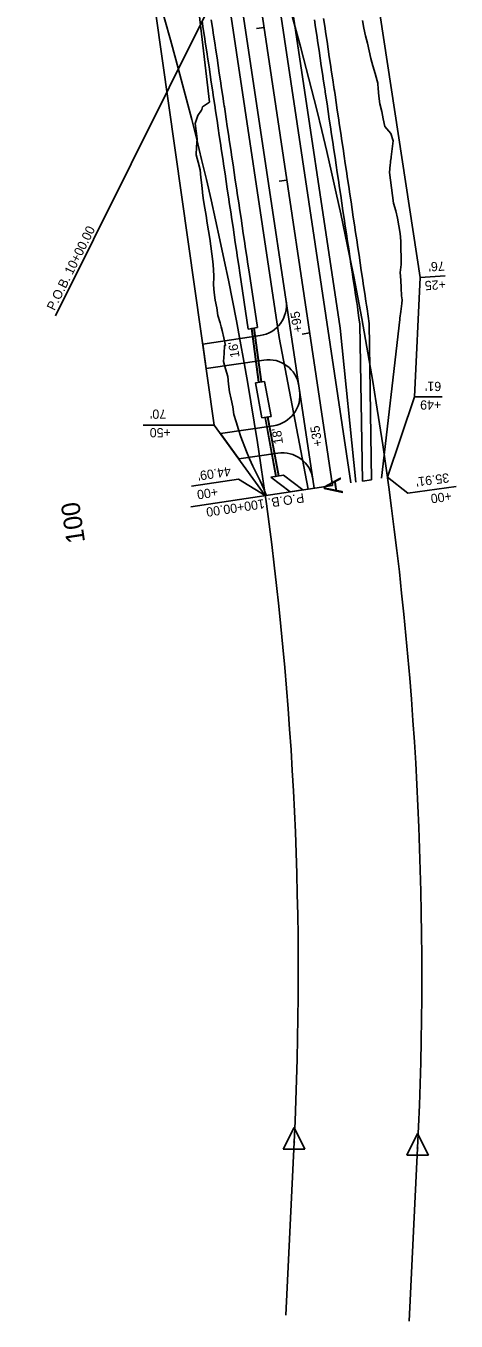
# Model space of a CAD drawing. Extents: x 609264 to 611265, y 427753 to 431566.
# Drawn here: x 610909 to 611188, y 427753 to 428592 of the extents above; entities that cross this region are included whole.
import ezdxf

# ---------------------------------------------------------------- set-up
doc = ezdxf.new("R2010")
doc.units = 0
for name, color, linetype in [('R_Drainage', 7, 'Continuous'), ('R_Drainage Stage 2', 7, 'Continuous'), ('R_Drive Annot Stage 2', 7, 'Continuous'), ('R_Drive Stage 2', 7, 'Continuous'), ('R_Horz Alg', 7, 'Continuous'), ('R_Horz Alg Station', 7, 'Continuous'), ('R_Horz Alg Station Annot', 7, 'Continuous'), ('R_Proposed Const Limits', 7, 'Continuous'), ('R_Proposed Const Limits S2', 7, 'Continuous'), ('R_Proposed Road', 7, 'Continuous'), ('R_Proposed Road Stage 2', 7, 'Continuous'), ('R_Proposed Shoulder', 7, 'Continuous'), ('R_Proposed Shoulder Stage 2', 7, 'Continuous'), ('R_ROW', 7, 'Continuous'), ('R_ROW Annot', 7, 'Continuous'), ('S_EXIST_ROW', 7, 'Continuous')]:
    doc.layers.add(name, color=color, linetype=linetype)

msp = doc.modelspace()

# ---------------------------------------------------------------- linework, layer by layer
at = {"layer": 'R_Drainage'}
for p, q in [((611125.51, 428398.82), (611127.06, 428297.17)), ((611131.5, 428399.31), (611133.05, 428298.06)), ((611127.06, 428297.17), (611133.05, 428298.06))]:
    msp.add_line(p, q, dxfattribs=at)
for points in [[(611131.5, 428399.31), (611130.82, 428403.9), (611130.08, 428408.84), (611129.74, 428411.1), (611129.34, 428413.79), (611128.6, 428418.73), (611127.86, 428423.68), (611127.12, 428428.62), (611126.38, 428433.57), (611125.64, 428438.51), (611124.9, 428443.46), (611124.16, 428448.4), (611123.42, 428453.35), (611122.68, 428458.29), (611121.94, 428463.24), (611121.2, 428468.18), (611120.46, 428473.13), (611119.72, 428478.07), (611118.98, 428483.02), (611118.24, 428487.96), (611117.5, 428492.91), (611116.76, 428497.85), (611116.02, 428502.8), (611115.28, 428507.74), (611114.54, 428512.69), (611113.8, 428517.63), (611113.06, 428522.58), (611112.32, 428527.52), (611111.58, 428532.47), (611110.84, 428537.41), (611110.1, 428542.36), (611109.36, 428547.3), (611108.92, 428550.27), (611108.84, 428550.79), (611108.62, 428552.25), (611107.88, 428557.19), (611107.14, 428562.14), (611106.4, 428567.08), (611105.66, 428572.03), (611104.92, 428576.97), (611104.18, 428581.92), (611103.44, 428586.86), (611102.7, 428591.81), (611101.96, 428596.75)], [(611125.51, 428398.82), (611124.88, 428403.01), (611124.14, 428407.96), (611123.81, 428410.21), (611123.4, 428412.9), (611122.66, 428417.85), (611121.92, 428422.79), (611121.18, 428427.74), (611120.44, 428432.68), (611119.7, 428437.63), (611118.96, 428442.57), (611118.22, 428447.52), (611117.48, 428452.46), (611116.74, 428457.41), (611116, 428462.35), (611115.26, 428467.3), (611114.52, 428472.24), (611113.78, 428477.19), (611113.05, 428482.13), (611112.31, 428487.08), (611111.57, 428492.02), (611110.83, 428496.97), (611110.09, 428501.91), (611109.35, 428506.86), (611108.61, 428511.8), (611107.87, 428516.75), (611107.13, 428521.69), (611106.39, 428526.64), (611105.65, 428531.58), (611104.91, 428536.53), (611104.17, 428541.47), (611103.43, 428546.42), (611102.98, 428549.38), (611102.9, 428549.91), (611102.69, 428551.36), (611101.95, 428556.31), (611101.21, 428561.25), (611100.47, 428566.2), (611099.73, 428571.14), (611098.99, 428576.09), (611098.25, 428581.03), (611097.51, 428585.97), (611096.77, 428590.92), (611096.03, 428595.86)]]:
    msp.add_lwpolyline(points, dxfattribs=at)
at = {"layer": 'R_Drainage Stage 2'}
for p, q in [((611047.74, 428432.01), (611053.18, 428395.68)), ((611053.7, 428432.71), (611059.11, 428396.57)), ((611053.18, 428395.68), (611059.11, 428396.57)), ((611055.24, 428396), (611057.05, 428396.24)), ((611055.24, 428396), (611059.85, 428361.18)), ((611055.4, 428396.03), (611060.01, 428361.2)), ((611056.89, 428396.22), (611061.5, 428361.4)), ((611057.05, 428396.24), (611061.66, 428361.42)), ((611057.79, 428360.86), (611063.72, 428361.75)), ((611059.85, 428361.18), (611061.66, 428361.42)), ((611063.72, 428361.75), (611067.92, 428339.05)), ((611057.79, 428360.86), (611061.99, 428338.16)), ((611067.92, 428339.05), (611061.99, 428338.16)), ((611064.05, 428338.44), (611065.86, 428338.77)), ((611064.05, 428338.44), (611071.13, 428300.19)), ((611064.22, 428338.47), (611071.29, 428300.22)), ((611065.69, 428338.74), (611072.77, 428300.5)), ((611065.86, 428338.77), (611072.93, 428300.53)), ((611076.04, 428300.96), (611067.77, 428299.72)), ((611067.77, 428299.72), (611080.29, 428290.17)), ((611071.13, 428300.19), (611072.93, 428300.53)), ((611076.04, 428300.96), (611088.55, 428291.41)), ((611080.29, 428290.17), (611088.55, 428291.41))]:
    msp.add_line(p, q, dxfattribs=at)
for points in [[(611047.75, 428431.96), (611047.02, 428436.86), (611046.28, 428441.81), (611045.54, 428446.75), (611044.8, 428451.7), (611044.06, 428456.64), (611043.32, 428461.59), (611042.58, 428466.53), (611041.84, 428471.48), (611041.1, 428476.42), (611040.36, 428481.37), (611039.62, 428486.31), (611038.88, 428491.26), (611038.14, 428496.2), (611037.4, 428501.15), (611036.66, 428506.09), (611035.92, 428511.04), (611035.18, 428515.98), (611034.44, 428520.93), (611033.7, 428525.87), (611032.96, 428530.82), (611032.22, 428535.76), (611031.77, 428538.73), (611031.7, 428539.25), (611031.48, 428540.71), (611030.74, 428545.65), (611030, 428550.6), (611029.26, 428555.54), (611028.52, 428560.49), (611027.78, 428565.43), (611027.04, 428570.38), (611026.3, 428575.32), (611025.56, 428580.27), (611024.82, 428585.21), (611024.08, 428590.16), (611023.34, 428595.1)], [(611053.7, 428432.76), (611052.95, 428437.75), (611052.21, 428442.69), (611051.47, 428447.64), (611050.73, 428452.58), (611049.99, 428457.53), (611049.25, 428462.47), (611048.51, 428467.42), (611047.77, 428472.36), (611047.03, 428477.31), (611046.29, 428482.25), (611045.55, 428487.2), (611044.81, 428492.14), (611044.07, 428497.09), (611043.33, 428502.03), (611042.59, 428506.98), (611041.85, 428511.92), (611041.11, 428516.87), (611040.37, 428521.81), (611039.63, 428526.76), (611038.89, 428531.7), (611038.15, 428536.65), (611037.71, 428539.62), (611037.63, 428540.14), (611037.41, 428541.59), (611036.67, 428546.54), (611035.93, 428551.48), (611035.19, 428556.43), (611034.45, 428561.37), (611033.71, 428566.32), (611032.97, 428571.26), (611032.23, 428576.21), (611031.49, 428581.15), (611030.75, 428586.1), (611030.01, 428591.04), (611029.27, 428595.99)]]:
    msp.add_lwpolyline(points, dxfattribs=at)
at = {"layer": 'R_Drive Stage 2'}
for p, q in [((611023.72, 428385.85), (611060.9, 428391.41)), ((611023.72, 428385.85), (611025.97, 428370.01)), ((611025.97, 428370.01), (611063.26, 428375.59)), ((611035.12, 428327.9), (611069.63, 428333.06)), ((611035.12, 428327.9), (611047.01, 428311.48)), ((611047.01, 428311.48), (611072.29, 428315.26))]:
    msp.add_line(p, q, dxfattribs=at)
for centre, start, end in [((611057.94, 428411.19), 278.50997, 8.50997), ((611066.22, 428355.81), 8.50997, 98.50997), ((611066.67, 428352.84), 278.50997, 8.50997), ((611075.25, 428295.48), 8.50997, 98.50997)]:
    msp.add_arc(centre, 20, start, end, dxfattribs=at)
at = {"layer": 'R_Horz Alg'}
msp.add_line((611107.78, 428294.28), (610909.26, 429621.04), dxfattribs=at)
at = {"layer": 'R_Horz Alg Station'}
for points in [[(610928.44, 428404.22), (611050.9, 428650.77), (611053.62, 428656.25)], [(611058.45, 428590.24), (611063.39, 428590.98)], [(611073.24, 428491.34), (611078.19, 428492.08)], [(611088.04, 428392.44), (611092.99, 428393.18)], [(611107.78, 428294.28), (611016.06, 428280.56)]]:
    msp.add_lwpolyline(points, dxfattribs=at)
at = {"layer": 'R_Proposed Const Limits'}
msp.add_lwpolyline([(611127.06, 428595.45), (611127.97, 428590.53), (611129.08, 428585.64), (611130.41, 428580.79), (611131.39, 428575.88), (611132.45, 428570.98), (611133.85, 428566.14), (611135.26, 428561.29), (611136.68, 428556.45), (611137.09, 428555.02), (611137.07, 428554.48), (611137.27, 428551.48), (611137.72, 428546.49), (611138.32, 428541.53), (611139.59, 428536.66), (611140.58, 428531.75), (611141.71, 428526.87), (611145.46, 428522.37), (611146.94, 428517.54), (611146.34, 428512.39), (611145.72, 428507.24), (611145.64, 428506.62), (611145.5, 428505.49), (611145.35, 428504.35), (611145.21, 428503.22), (611144.96, 428502.07), (611144.54, 428496.95), (611145.21, 428492), (611145.89, 428487.05), (611146.52, 428482.08), (611147.22, 428477.13), (611148.67, 428472.29), (611149.85, 428467.42), (611151.59, 428457.56), (611151.86, 428452.55), (611151.91, 428447.5), (611152.24, 428442.49), (611152.17, 428437.43), (611151.5, 428432.27), (611151.93, 428427.28), (611152.26, 428422.28), (611152.47, 428417.25), (611152.82, 428414.55), (611152.7, 428412.23), (611152.06, 428407.08), (611151.42, 428402.79), (611151.32, 428401.91), (611139.38, 428298.98)], dxfattribs=at)
at = {"layer": 'R_Proposed Const Limits S2'}
for points in [[(611028.03, 428542.72), (611021.49, 428599.88)], [(611030.82, 428429.36), (611030.82, 428429.38), (611030.69, 428434.42), (611030.27, 428439.41), (611029.72, 428444.38), (611029.02, 428449.34), (611028.37, 428454.29), (611027.47, 428459.22), (611026.61, 428464.14), (611025.98, 428469.1), (611025.02, 428474.02), (611024.2, 428478.95), (611023.58, 428483.91), (611023.48, 428485.01), (611023.37, 428486.1), (611023.26, 428487.2), (611023.18, 428488.29), (611023.13, 428488.9), (611022.59, 428493.88), (611022, 428498.84), (611020.86, 428503.73), (611019.56, 428508.59), (611019.64, 428513.66), (611020.03, 428518.77), (611019.53, 428523.75), (611018.88, 428528.71), (611020.49, 428534.01), (611022.89, 428537.4), (611023.08, 428537.96), (611023.6, 428539.53), (611028.03, 428542.72)], [(611064.94, 428287.87), (611064.65, 428288.61), (611063.05, 428292.65), (611060.89, 428297.38), (611058.48, 428302.07), (611056.11, 428306.77), (611053.95, 428311.51), (611052.03, 428316.28), (611048.45, 428325.85), (611046.81, 428330.66), (611045.37, 428335.5), (611043.91, 428340.34), (611043.17, 428345.28), (611042.14, 428350.19), (611041, 428355.07), (611040.38, 428360.03), (611039.92, 428365.02), (611038.52, 428369.87), (611037.15, 428374.72), (611037.54, 428379.83), (611037.71, 428384.91), (611038.45, 428385.02), (611037.34, 428389.91), (611036.23, 428394.8), (611035.74, 428397.03), (611034.95, 428399.67), (611033.55, 428404.51), (611032.8, 428409.46), (611031.84, 428414.37), (611031.14, 428419.32), (611030.74, 428424.31), (611030.82, 428429.38)]]:
    msp.add_lwpolyline(points, dxfattribs=at)
at = {"layer": 'R_Proposed Road'}
for p, q in [((611100.64, 428423.11), (610921.13, 429622.82)), ((611119.65, 428296.06), (611100.64, 428423.11))]:
    msp.add_line(p, q, dxfattribs=at)
at = {"layer": 'R_Proposed Road Stage 2'}
msp.add_line((611095.92, 428292.51), (611041.57, 428655.73), dxfattribs=at)
at = {"layer": 'R_Proposed Shoulder'}
for p, q in [((611112.77, 428396.14), (610929.04, 429624)), ((611122.86, 428296.54), (611112.77, 428396.14))]:
    msp.add_line(p, q, dxfattribs=at)
at = {"layer": 'R_Proposed Shoulder Stage 2'}
for p, q in [((611073.21, 428390.22), (611025.84, 428706.82)), ((611091.95, 428291.92), (611073.21, 428390.22))]:
    msp.add_line(p, q, dxfattribs=at)
at = {"layer": 'R_ROW'}
for points in [[(611143.3, 428299.6), (611160.86, 428351.77), (611164.45, 428429.15), (611122.21, 428706.36), (611107.97, 428799.88)], [(611064.18, 428287.76), (611031.16, 428333.38), (610989.06, 428630.42)]]:
    msp.add_lwpolyline(points, dxfattribs=at)
at = {"layer": 'R_ROW Annot'}
for p, q in [((611164.45, 428429.15), (611180.73, 428430.08)), ((611160.86, 428351.77), (611178.8, 428351.77)), ((610985.16, 428333.38), (611031.16, 428333.38)), ((611016.45, 428293.79), (611046.94, 428298.35)), ((611064.18, 428287.76), (611046.94, 428298.35)), ((611143.3, 428299.6), (611156.55, 428289.4)), ((611156.55, 428289.4), (611187.73, 428293.66))]:
    msp.add_line(p, q, dxfattribs=at)
at = {"layer": 'S_EXIST_ROW'}
for p, q in [((611082.91, 427878.51), (611075.86, 427864.32)), ((611082.91, 427878.51), (611089.88, 427864.32)), ((611162.82, 427874.62), (611155.76, 427860.44)), ((611162.82, 427874.62), (611169.79, 427860.44)), ((611077.44, 427756.93), (611082.88, 427869.05)), ((611082.88, 427869.05), (611082.88, 427869.05)), ((611075.86, 427864.32), (611089.88, 427864.32)), ((611155.76, 427860.44), (611169.79, 427860.44)), ((611157.34, 427753.05), (611162.79, 427865.17)), ((611162.79, 427865.17), (611162.79, 427865.17))]:
    msp.add_line(p, q, dxfattribs=at)
for centre, radius in [((611082.88, 427869.05), 0.24), ((611082.88, 427869.05), 0.12), ((611162.79, 427865.17), 0.24), ((611162.79, 427865.17), 0.12)]:
    msp.add_circle(centre, radius, dxfattribs=at)
for radius in [2331.83, 2251.83]:
    msp.add_arc((608833.71, 427978.36), radius, 357.21778, 18.98444, dxfattribs=at)

# ---------------------------------------------------------------- texts
at = {"layer": 'R_Drive Annot Stage 2'}
for s, rotation, p in [('+95', 99.05933, (611088.39, 428394.07)), ("16'", 98.62675, (611047.59, 428377.54)), ("18'", 98.62675, (611075.77, 428321.49)), ('+35', 99.05933, (611101.25, 428320))]:
    msp.add_text(s, height=6, rotation=rotation, dxfattribs=at).set_placement(p)
at = {"layer": 'R_Horz Alg'}
msp.add_text('A', height=12, rotation=98.50997, dxfattribs=at).set_placement((611114.61, 428289.24))
at = {"layer": 'R_Horz Alg Station Annot'}
for s, height, rotation, p in [('P.O.B. 10+00.00', 6, 63.58654, (610927.79, 428407.15)), ('P.O.B. 100+00.00', 6, 188.50997, (611088.92, 428289.37)), ('100', 12, 98.50997, (610947.61, 428257.78))]:
    msp.add_text(s, height=height, rotation=rotation, dxfattribs=at).set_placement(p)
at = {"layer": 'R_ROW Annot'}
for s, rotation, p in [("76'", 183.26254, (611180.19, 428439.49)), ('+25', 183.26254, (611180.88, 428427.51)), ("61'", 180, (611178.11, 428361.47)), ('+49', 180, (611178.11, 428349.47)), ("70'", 180, (611000.04, 428343.52)), ('+50', 180, (611003.02, 428331.52)), ("44.09'", 188.50997, (611041.45, 428306.57)), ("35.91'", 187.79005, (611182.8, 428302.35)), ('+00', 188.50997, (611033.09, 428293.18)), ('+00', 187.79005, (611184.43, 428290.46))]:
    msp.add_text(s, height=6, rotation=rotation, dxfattribs=at).set_placement(p)

doc.saveas('drawing.dxf')
